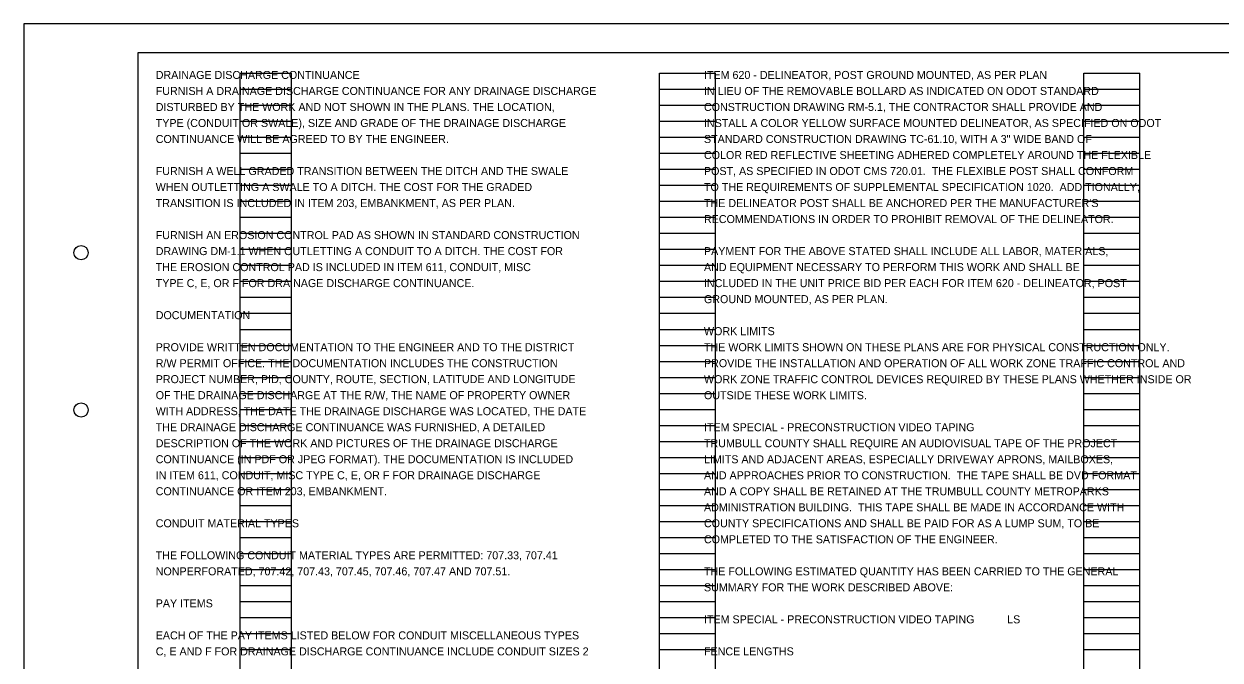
# Model space of a CAD drawing. Extents: x -16 to 195, y -13 to 9.
# Drawn here: x 27.86 to 48.79, y -2.03 to 9.09 of the extents above; entities that cross this region are included whole.
import ezdxf

# ---------------------------------------------------------------- set-up
doc = ezdxf.new("R2010")
doc.units = 0
for name, color, linetype in [('SH_Border', 7, 'Continuous'), ('SH_Cut_Line', 7, 'Continuous'), ('SH_Data', 7, 'Continuous'), ('TX_P_1', 7, 'Continuous')]:
    doc.layers.add(name, color=color, linetype=linetype)

msp = doc.modelspace()

# ---------------------------------------------------------------- linework, layer by layer
at = {"layer": 'SH_Border'}
msp.add_lwpolyline([(29.861, 8.593), (61.361, 8.593), (61.361, -12.407), (29.861, -12.407)], close=True, dxfattribs=at)
for centre in [(28.861, 5.093), (28.861, 2.343)]:
    msp.add_circle(centre, 0.125, dxfattribs=at)
at = {"layer": 'SH_Cut_Line'}
msp.add_lwpolyline([(27.861, -12.907), (61.861, -12.907), (61.861, 9.093), (27.861, 9.093)], close=True, dxfattribs=at)
at = {"layer": 'SH_Data'}
for p, q in [((31.642, -11.927), (31.642, 8.233)), ((31.642, 8.233), (32.542, 8.233)), ((32.542, -11.927), (32.542, 8.233)), ((38.982, -11.927), (38.982, 8.233)), ((38.982, 8.233), (39.962, 8.233)), ((39.962, -11.927), (39.962, 8.233)), ((46.402, -11.927), (46.402, 8.233)), ((46.402, 8.233), (47.382, 8.233)), ((47.382, -11.927), (47.382, 8.233)), ((31.642, 7.953), (32.542, 7.953)), ((38.982, 7.953), (39.962, 7.953)), ((46.402, 7.953), (47.382, 7.953)), ((31.642, 7.673), (32.542, 7.673)), ((38.982, 7.673), (39.962, 7.673)), ((46.402, 7.673), (47.382, 7.673)), ((31.642, 7.393), (32.542, 7.393)), ((38.982, 7.393), (39.962, 7.393)), ((46.402, 7.393), (47.382, 7.393)), ((31.642, 7.113), (32.542, 7.113)), ((38.982, 7.113), (39.962, 7.113)), ((46.402, 7.113), (47.382, 7.113)), ((31.642, 6.833), (32.542, 6.833)), ((38.982, 6.833), (39.962, 6.833)), ((46.402, 6.833), (47.382, 6.833)), ((31.642, 6.553), (32.542, 6.553)), ((38.982, 6.553), (39.962, 6.553)), ((46.402, 6.553), (47.382, 6.553)), ((31.642, 6.273), (32.542, 6.273)), ((38.982, 6.273), (39.962, 6.273)), ((46.402, 6.273), (47.382, 6.273)), ((31.642, 5.993), (32.542, 5.993)), ((38.982, 5.993), (39.962, 5.993)), ((46.402, 5.993), (47.382, 5.993)), ((31.642, 5.713), (32.542, 5.713)), ((38.982, 5.713), (39.962, 5.713)), ((46.402, 5.713), (47.382, 5.713)), ((31.642, 5.433), (32.542, 5.433)), ((38.982, 5.433), (39.962, 5.433)), ((46.402, 5.433), (47.382, 5.433)), ((31.642, 5.153), (32.542, 5.153)), ((38.982, 5.153), (39.962, 5.153)), ((46.402, 5.153), (47.382, 5.153)), ((31.642, 4.873), (32.542, 4.873)), ((38.982, 4.873), (39.962, 4.873)), ((46.402, 4.873), (47.382, 4.873)), ((31.642, 4.593), (32.542, 4.593)), ((38.982, 4.593), (39.962, 4.593)), ((46.402, 4.593), (47.382, 4.593)), ((31.642, 4.313), (32.542, 4.313)), ((38.982, 4.313), (39.962, 4.313)), ((46.402, 4.313), (47.382, 4.313)), ((31.642, 4.033), (32.542, 4.033)), ((38.982, 4.033), (39.962, 4.033)), ((46.402, 4.033), (47.382, 4.033)), ((31.642, 3.753), (32.542, 3.753)), ((38.982, 3.753), (39.962, 3.753)), ((46.402, 3.753), (47.382, 3.753)), ((31.642, 3.473), (32.542, 3.473)), ((38.982, 3.473), (39.962, 3.473)), ((46.402, 3.473), (47.382, 3.473)), ((31.642, 3.193), (32.542, 3.193)), ((38.982, 3.193), (39.962, 3.193)), ((46.402, 3.193), (47.382, 3.193)), ((31.642, 2.913), (32.542, 2.913)), ((38.982, 2.913), (39.962, 2.913)), ((46.402, 2.913), (47.382, 2.913)), ((31.642, 2.633), (32.542, 2.633)), ((38.982, 2.633), (39.962, 2.633)), ((46.402, 2.633), (47.382, 2.633)), ((31.642, 2.353), (32.542, 2.353)), ((38.982, 2.353), (39.962, 2.353)), ((46.402, 2.353), (47.382, 2.353)), ((31.642, 2.073), (32.542, 2.073)), ((38.982, 2.073), (39.962, 2.073)), ((46.402, 2.073), (47.382, 2.073)), ((31.642, 1.793), (32.542, 1.793)), ((38.982, 1.793), (39.962, 1.793)), ((46.402, 1.793), (47.382, 1.793)), ((31.642, 1.513), (32.542, 1.513)), ((38.982, 1.513), (39.962, 1.513)), ((46.402, 1.513), (47.382, 1.513)), ((31.642, 1.233), (32.542, 1.233)), ((38.982, 1.233), (39.962, 1.233)), ((46.402, 1.233), (47.382, 1.233)), ((31.642, 0.953), (32.542, 0.953)), ((38.982, 0.953), (39.962, 0.953)), ((46.402, 0.953), (47.382, 0.953)), ((31.642, 0.673), (32.542, 0.673)), ((38.982, 0.673), (39.962, 0.673)), ((46.402, 0.673), (47.382, 0.673)), ((31.642, 0.393), (32.542, 0.393)), ((38.982, 0.393), (39.962, 0.393)), ((46.402, 0.393), (47.382, 0.393)), ((31.642, 0.113), (32.542, 0.113)), ((38.982, 0.113), (39.962, 0.113)), ((46.402, 0.113), (47.382, 0.113)), ((31.642, -0.167), (32.542, -0.167)), ((38.982, -0.167), (39.962, -0.167)), ((46.402, -0.167), (47.382, -0.167)), ((31.642, -0.447), (32.542, -0.447)), ((38.982, -0.447), (39.962, -0.447)), ((46.402, -0.447), (47.382, -0.447)), ((31.642, -0.727), (32.542, -0.727)), ((38.982, -0.727), (39.962, -0.727)), ((46.402, -0.727), (47.382, -0.727)), ((31.642, -1.007), (32.542, -1.007)), ((38.982, -1.007), (39.962, -1.007)), ((46.402, -1.007), (47.382, -1.007)), ((31.642, -1.287), (32.542, -1.287)), ((38.982, -1.287), (39.962, -1.287)), ((46.402, -1.287), (47.382, -1.287)), ((31.642, -1.567), (32.542, -1.567)), ((38.982, -1.567), (39.962, -1.567)), ((46.402, -1.567), (47.382, -1.567)), ((31.642, -1.847), (32.542, -1.847)), ((38.982, -1.847), (39.962, -1.847)), ((46.402, -1.847), (47.382, -1.847))]:
    msp.add_line(p, q, dxfattribs=at)

# ---------------------------------------------------------------- texts
at = {"layer": 'TX_P_1'}
for s, p in [('DRAINAGE DISCHARGE CONTINUANCE', (30.167, 8.131)), ('ITEM 620 - DELINEATOR, POST GROUND MOUNTED, AS PER PLAN', (39.758, 8.131)), ('FURNISH A DRAINAGE DISCHARGE CONTINUANCE FOR ANY DRAINAGE DISCHARGE', (30.167, 7.851)), ('IN LIEU OF THE REMOVABLE BOLLARD AS INDICATED ON ODOT STANDARD', (39.758, 7.851)), ('DISTURBED BY THE WORK AND NOT SHOWN IN THE PLANS. THE LOCATION,', (30.167, 7.571)), ('CONSTRUCTION DRAWING RM-5.1, THE CONTRACTOR SHALL PROVIDE AND', (39.758, 7.571)), ('TYPE (CONDUIT OR SWALE), SIZE AND GRADE OF THE DRAINAGE DISCHARGE', (30.167, 7.291)), ('INSTALL A COLOR YELLOW SURFACE MOUNTED DELINEATOR, AS SPECIFIED ON ODOT', (39.758, 7.291)), ('CONTINUANCE WILL BE AGREED TO BY THE ENGINEER.', (30.167, 7.011)), ('STANDARD CONSTRUCTION DRAWING TC-61.10, WITH A 3" WIDE BAND OF ', (39.758, 7.011)), ('COLOR RED REFLECTIVE SHEETING ADHERED COMPLETELY AROUND THE FLEXIBLE', (39.758, 6.731)), ('FURNISH A WELL GRADED TRANSITION BETWEEN THE DITCH AND THE SWALE', (30.167, 6.451)), ('POST, AS SPECIFIED IN ODOT CMS 720.01.  THE FLEXIBLE POST SHALL CONFORM', (39.758, 6.451)), ('WHEN OUTLETTING A SWALE TO A DITCH. THE COST FOR THE GRADED', (30.167, 6.171)), ('TO THE REQUIREMENTS OF SUPPLEMENTAL SPECIFICATION 1020.  ADDITIONALLY,', (39.758, 6.171)), ('TRANSITION IS INCLUDED IN ITEM 203, EMBANKMENT, AS PER PLAN.', (30.167, 5.891)), ("THE DELINEATOR POST SHALL BE ANCHORED PER THE MANUFACTURER'S", (39.758, 5.891)), ('RECOMMENDATIONS IN ORDER TO PROHIBIT REMOVAL OF THE DELINEATOR.', (39.758, 5.611)), ('FURNISH AN EROSION CONTROL PAD AS SHOWN IN STANDARD CONSTRUCTION', (30.167, 5.331)), ('DRAWING DM-1.1 WHEN OUTLETTING A CONDUIT TO A DITCH. THE COST FOR', (30.167, 5.051)), ('PAYMENT FOR THE ABOVE STATED SHALL INCLUDE ALL LABOR, MATERIALS,', (39.758, 5.051)), ('THE EROSION CONTROL PAD IS INCLUDED IN ITEM 611, CONDUIT, MISC', (30.167, 4.771)), ('AND EQUIPMENT NECESSARY TO PERFORM THIS WORK AND SHALL BE ', (39.758, 4.771)), ('TYPE C, E, OR F FOR DRAINAGE DISCHARGE CONTINUANCE.', (30.167, 4.491)), ('INCLUDED IN THE UNIT PRICE BID PER EACH FOR ITEM 620 - DELINEATOR, POST', (39.758, 4.491)), ('GROUND MOUNTED, AS PER PLAN.', (39.758, 4.211)), ('DOCUMENTATION', (30.167, 3.931)), ('WORK LIMITS', (39.758, 3.651)), ('PROVIDE WRITTEN DOCUMENTATION TO THE ENGINEER AND TO THE DISTRICT', (30.167, 3.371)), ('THE WORK LIMITS SHOWN ON THESE PLANS ARE FOR PHYSICAL CONSTRUCTION ONLY. ', (39.758, 3.371)), ('R/W PERMIT OFFICE. THE DOCUMENTATION INCLUDES THE CONSTRUCTION', (30.167, 3.091)), ('PROVIDE THE INSTALLATION AND OPERATION OF ALL WORK ZONE TRAFFIC CONTROL AND ', (39.758, 3.091)), ('PROJECT NUMBER, PID, COUNTY, ROUTE, SECTION, LATITUDE AND LONGITUDE', (30.167, 2.812)), ('WORK ZONE TRAFFIC CONTROL DEVICES REQUIRED BY THESE PLANS WHETHER INSIDE OR ', (39.758, 2.811)), ('OF THE DRAINAGE DISCHARGE AT THE R/W, THE NAME OF PROPERTY OWNER', (30.167, 2.532)), ('OUTSIDE THESE WORK LIMITS.', (39.758, 2.531)), ('WITH ADDRESS, THE DATE THE DRAINAGE DISCHARGE WAS LOCATED, THE DATE', (30.167, 2.252)), ('THE DRAINAGE DISCHARGE CONTINUANCE WAS FURNISHED, A DETAILED', (30.167, 1.972)), ('ITEM SPECIAL - PRECONSTRUCTION VIDEO TAPING', (39.758, 1.971)), ('DESCRIPTION OF THE WORK AND PICTURES OF THE DRAINAGE DISCHARGE', (30.167, 1.692)), ('TRUMBULL COUNTY SHALL REQUIRE AN AUDIOVISUAL TAPE OF THE PROJECT', (39.758, 1.691)), ('CONTINUANCE (IN PDF OR JPEG FORMAT). THE DOCUMENTATION IS INCLUDED', (30.167, 1.412)), ('LIMITS AND ADJACENT AREAS, ESPECIALLY DRIVEWAY APRONS, MAILBOXES, ', (39.758, 1.411)), ('IN ITEM 611, CONDUIT, MISC TYPE C, E, OR F FOR DRAINAGE DISCHARGE', (30.167, 1.132)), ('AND APPROACHES PRIOR TO CONSTRUCTION.  THE TAPE SHALL BE DVD FORMAT', (39.758, 1.131)), ('CONTINUANCE OR ITEM 203, EMBANKMENT.', (30.167, 0.852)), ('AND A COPY SHALL BE RETAINED AT THE TRUMBULL COUNTY METROPARKS', (39.758, 0.851)), ('ADMINISTRATION BUILDING.  THIS TAPE SHALL BE MADE IN ACCORDANCE WITH', (39.758, 0.571)), ('CONDUIT MATERIAL TYPES', (30.167, 0.292)), ('COUNTY SPECIFICATIONS AND SHALL BE PAID FOR AS A LUMP SUM, TO BE', (39.758, 0.292)), ('COMPLETED TO THE SATISFACTION OF THE ENGINEER.', (39.758, 0.012)), ('THE FOLLOWING CONDUIT MATERIAL TYPES ARE PERMITTED: 707.33, 707.41', (30.167, -0.268)), ('NONPERFORATED, 707.42, 707.43, 707.45, 707.46, 707.47 AND 707.51.', (30.167, -0.548)), ('THE FOLLOWING ESTIMATED QUANTITY HAS BEEN CARRIED TO THE GENERAL', (39.758, -0.548)), ('SUMMARY FOR THE WORK DESCRIBED ABOVE:', (39.758, -0.828)), ('PAY ITEMS', (30.167, -1.108)), ('ITEM SPECIAL - PRECONSTRUCTION VIDEO TAPING           LS', (39.758, -1.388)), ('EACH OF THE PAY ITEMS LISTED BELOW FOR CONDUIT MISCELLANEOUS TYPES', (30.167, -1.668)), ('C, E AND F FOR DRAINAGE DISCHARGE CONTINUANCE INCLUDE CONDUIT SIZES 2 ', (30.167, -1.948)), ('FENCE LENGTHS', (39.758, -1.948))]:
    msp.add_text(s, height=0.14, dxfattribs=at).set_placement(p)

doc.saveas('drawing.dxf')
